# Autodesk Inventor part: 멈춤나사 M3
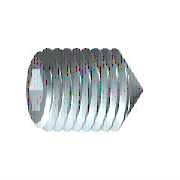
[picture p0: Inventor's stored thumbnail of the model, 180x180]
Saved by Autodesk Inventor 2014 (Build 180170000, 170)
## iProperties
IsCustomPart: 1
Created: 2012-02
Part Number: 멈춤나사 M3
Material: 강철, 연강
Description: 6각 소켓 머리 없는 멈춤 나사
Document SubType Name: Modeling
Standard: KS B 1028
Designer: test
Standards Organization: KS
Language: ko-KR
Size Designation: 원추점 M3x8
Categories: <MemberInstance><Categories><Category DisplayName="조임쇠" InternalName="e4da775c-781d-43d5-af7c-5136215cf5a6" Mnemonic="FSTN"><Category DisplayName="볼트" InternalN
Density: 1 g/cm^3
Appearance: 강철
Author: test
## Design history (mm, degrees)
sketch "스케치1"
  geometry: L1 (0, 0)-(3.5, 0); L2 (6, 0.866)-(6, 1.5); L3 (6, 1.5)-(0, 1.5); L4 (6, 0.866)-(4, 0.866); L5 (4, 0.866)-(3.5, 0); L6 (0, -0.3)-(0, 1.8) reference; L7 (0, 1.5)-(0, 0)
  constraints: 13 end point, 3 parallel, 1 collinear, 1 perpendicular, 1 point on line
  dimensions: "d0" = 2 distance of L2.start L4.end (= INTI); "d1" = 60 deg angle of L5 L1; "d2" = 3 diameter of L3 L1 (= NND); "d3" = 1.73205 diameter of L4 L1 (= 1.1547 x SW); "d5" = 6 distance from line of L2 L3.end (= NLG)
revolve "본체" sketch "스케치1" stored, may be unused: angle "d6" = 90 deg
sketch "스케치2"
  geometry: L1 (-0.433, 0.75)-(0.433, 0.75); L2 (0.433, 0.75)-(0.866, 0); L3 (0.866, 0)-(0.433, -0.75); L4 (0.433, -0.75)-(-0.433, -0.75); L5 (-0.433, -0.75)-(-0.866, 0); L6 (-0.866, 0)-(-0.433, 0.75); 3 further points
  constraints: 12 end point, 1 coincident, 1 horizontal, 13 other
extrude "슬롯" join sketch "스케치2" taper "d7" = 0 deg; stored distance "d21" = 10
workaxis "Work Axis1"
workplane "Work Plane1"
sketch "스케치4"
  geometry: L1 (0, 0.15)-(-1.35, 1.5) reference; L2 (0, -0.15)-(-1.35, -1.5) reference; L3 (-1.35, -1.5)-(0.15, 0); L4 (-1.35, 1.5)-(0.15, 0); 2 further points
  constraints: 4 end point, 1 coincident, 1 collinear, 1 horizontal alignment
node "작업점1"
body "Solid1"
feature "스레드" dims "d12" = 6 (= NLG), "d13" = 0
chamfer "모따기1" distance "d8" = 1.35 (computed from NND, SPD, FAWI); stored, may be unused: angle "d9" = 45 deg (= FAWI), second distance "d34" = 1.35 (computed from NND, SPD, FAWI)
chamfer "모따기2" distance "d10" = 0.30673 (= -0.5 x GD1 + 0.5 x NND); stored, may be unused: angle "d11" = 45 deg (= FAWI), second distance "d35" = 0.30673 (= -0.5 x GD1 + 0.5 x NND)
other parameters: "NND" = 3 [user parameter; used in 5 equation terms], "NLG" = 6 [user parameter; used in 2 equation terms], "INTI" = 2 [user parameter; used in 1 equation term], "FAWI" = 45 deg [user parameter; used in 4 equation terms], "SW" = 1.5 [user parameter; used in 2 equation terms], "GD1" = 2.38655 (= THREADDIA - 1.2269 x PTC) [user parameter; used in 2 equation terms], "d4" = 0, "FAWI1" = 45 deg [user parameter], "SPD" = 0.3 [user parameter; used in 2 equation terms], "d36" = 0, "d37" = 0, "GUL" = 0.30673 (= 0.61345 x PTC) [user parameter], "TOA" = 30 deg [user parameter], "THREADDIA" = 3 [user parameter; used in 1 equation term], "PTC" = 0.5 [user parameter; used in 4 equation terms], "GAL" = 0.30673 (= 0.61345 x PTC) [user parameter], "E0" = 1.7325 (= 1.155 x SW) [user parameter]
